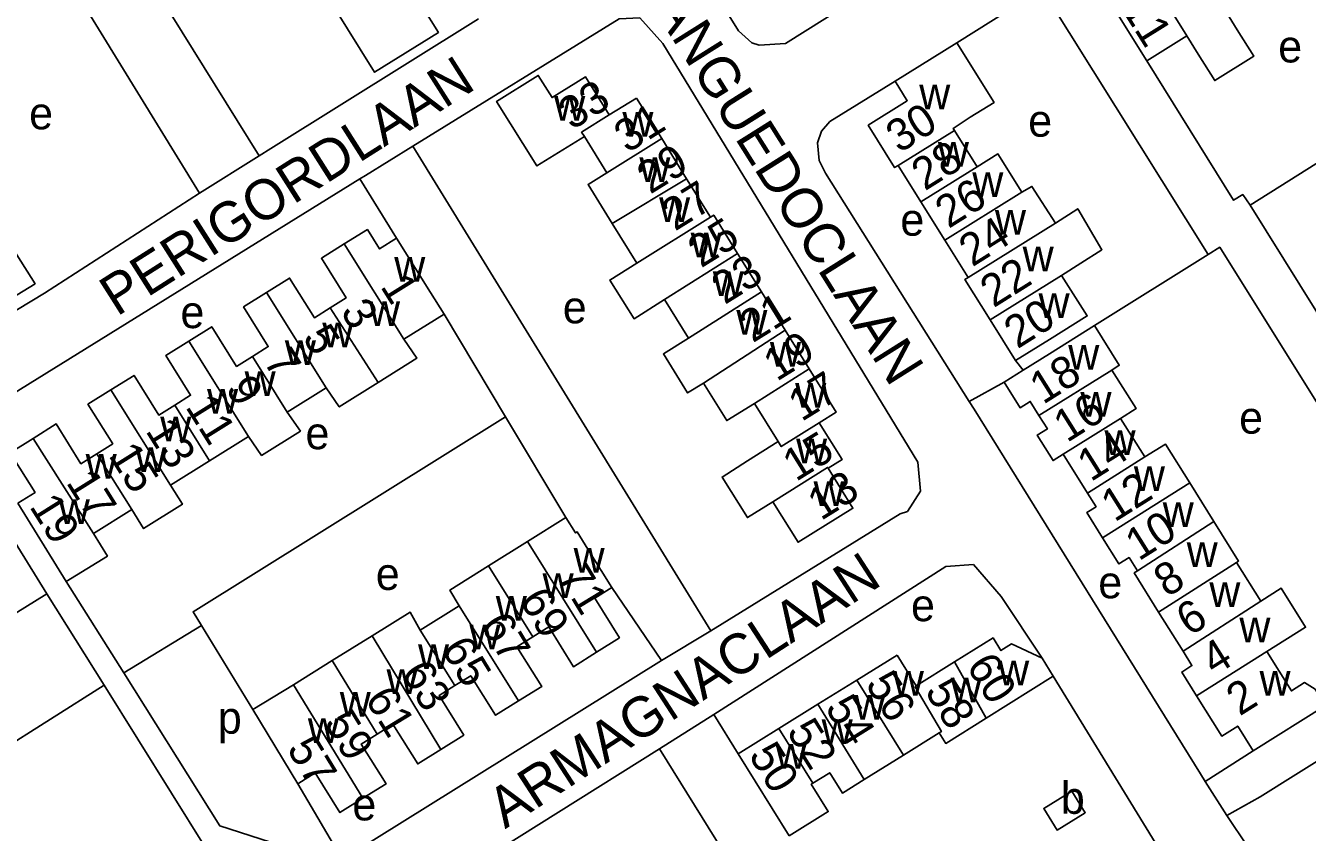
# Model space of a CAD drawing. Extents: x 157768 to 159790, y 387230 to 389604.
# Drawn here: x 158424 to 158583.5, y 388082.5 to 388182.9 of the extents above; entities that cross this region are included whole.
import ezdxf

# ---------------------------------------------------------------- set-up
doc = ezdxf.new("R2010")
doc.units = 0
for name, color, linetype in [('BLT_Basislijn', 7, 'Continuous'), ('BLT_Bebouwing', 7, 'Continuous'), ('BLT_Centroide', 7, 'Continuous'), ('BLT_Huisnummer', 7, 'Continuous'), ('BLT_Huisnummer_ tussenligend', 7, 'Continuous'), ('BLT_Onderverdeling_panden', 7, 'Continuous'), ('BLT_Straatnaam', 7, 'Continuous')]:
    doc.layers.add(name, color=color, linetype=linetype)

msp = doc.modelspace()

# ---------------------------------------------------------------- linework, layer by layer
at = {"layer": 'BLT_Basislijn'}
for p, q in [((158436.28, 388193.58), (158453.03, 388166.65)), ((158428.99, 388189.09), (158445.59, 388162)), ((158550.48, 388187.4), (158539.86, 388180.73)), ((158550.48, 388187.4), (158571.14, 388154.4)), ((158576.33, 388160.51), (158592.73, 388170.86)), ((158472.14, 388167.87), (158509.22, 388107.54)), ((158445.59, 388162), (158453.03, 388166.65)), ((158465.57, 388163.8), (158416.78, 388133.56)), ((158470.14, 388156.41), (158465.57, 388163.8)), ((158571.14, 388154.4), (158556.99, 388145.54)), ((158476.05, 388146.97), (158483.7, 388134.19)), ((158548.1, 388139.99), (158547.15, 388141.17)), ((158545.72, 388138.51), (158541.4, 388136.1)), ((158483.7, 388134.19), (158491.2, 388121.66)), ((158429.02, 388113.68), (158436.19, 388102.31)), ((158503.11, 388103.84), (158496.93, 388112.95)), ((158426.61, 388112.17), (158433.74, 388100.78)), ((158445.86, 388108.21), (158436.19, 388102.31)), ((158452.25, 388097.74), (158445.86, 388108.21)), ((158509.22, 388107.54), (158503.11, 388103.84)), ((158433.74, 388100.78), (158395.24, 388076.43)), ((158502.83, 388092.88), (158509.63, 388097.12)), ((158512.63, 388092.24), (158509.63, 388097.12)), ((158544.39, 388026.21), (158502.83, 388092.88)), ((158570.76, 388088.79), (158576.73, 388092.61)), ((158463.63, 388078.71), (158457.86, 388088.53)), ((158570.76, 388088.79), (158573.46, 388084.58))]:
    msp.add_line(p, q, dxfattribs=at)
for points in [[(158547.57, 388198.9), (158518.51, 388180.63), (158515.25, 388180.43), (158514.36, 388180.7), (158512.7, 388182.23), (158508.37, 388189.2), (158509.52, 388189.92)], [(158453.03, 388166.65), (158454.49, 388167.56), (158480.34, 388183.69)], [(158472.14, 388167.87), (158497.85, 388183.7), (158500.4, 388183.83), (158503.27, 388180.63), (158534.99, 388128.52), (158535.32, 388124.94), (158533.71, 388122.42), (158532.81, 388122.1), (158509.22, 388107.54)], [(158576.33, 388160.51), (158575.42, 388161.84), (158574.28, 388161.13), (158563.49, 388178.46)], [(158532.17, 388175.93), (158524.05, 388170.92), (158522.99, 388169.74), (158522.53, 388168.26), (158522.72, 388166.06), (158523.5, 388164.5), (158541.4, 388136.1)], [(158395.91, 388168.42), (158411.29, 388143.91), (158412.49, 388143.4), (158416.19, 388143.49), (158426.31, 388149.56), (158445.59, 388162)], [(158472.14, 388167.87), (158466.26, 388164.23), (158465.57, 388163.8)], [(158576.33, 388160.51), (158605.06, 388114.46), (158610.96, 388118.11), (158616.41, 388116.75), (158618.88, 388112.75)], [(158585.71, 388098.25), (158601.85, 388108.41), (158572.56, 388155.28), (158571.14, 388154.4)], [(158541.4, 388136.1), (158542.01, 388135.15), (158570.15, 388089.76), (158570.76, 388088.79)], [(158445.86, 388108.21), (158444.8, 388109.93), (158483.7, 388134.19)], [(158509.63, 388097.12), (158538.5, 388115.54), (158541.92, 388115.8), (158545.37, 388111.83), (158550.45, 388104.15)], [(158618.88, 388112.75), (158577.61, 388086.89), (158573.46, 388084.58)], [(158503.11, 388103.84), (158464.46, 388079.77), (158464.09, 388079.58), (158463.63, 388078.71)], [(158436.19, 388102.31), (158448.14, 388083.28), (158463.43, 388078.34)], [(158551.85, 388101.9), (158581.6, 388053.35), (158581.69, 388051.02), (158580.67, 388049.28), (158574.94, 388045.64)], [(158433.74, 388100.78), (158446.31, 388080.65), (158463.81, 388074.86)], [(158502.83, 388092.88), (158477.73, 388077.1), (158475.97, 388074.87), (158475.84, 388072.59), (158476.35, 388071.14), (158490.02, 388048.65), (158497.8, 388036.83), (158512.86, 388012.82), (158514.89, 388011.22), (158518.52, 388010.62), (158520.52, 388010.8), (158521.92, 388011.98)], [(158581.28, 388072.88), (158573.46, 388084.58)]]:
    msp.add_lwpolyline(points, dxfattribs=at)
at = {"layer": 'BLT_Bebouwing'}
for p, q in [((158558.84, 388185.9), (158563.49, 388178.46)), ((158539.86, 388180.73), (158532.17, 388175.93)), ((158496.57, 388171.77), (158500, 388173.84)), ((158503.12, 388168.81), (158500, 388173.84)), ((158496.29, 388164.55), (158493.5, 388169.05)), ((158506.22, 388163.8), (158503.12, 388168.81)), ((158539.55, 388169.83), (158542.38, 388165.28)), ((158532.54, 388165.46), (158535.36, 388160.95)), ((158509.19, 388159.02), (158506.22, 388163.8)), ((158535.36, 388160.95), (158538.34, 388156.17)), ((158500.02, 388153.31), (158496.97, 388158.24)), ((158538.34, 388156.17), (158541.24, 388151.53)), ((158515.54, 388149.73), (158512.57, 388154.51)), ((158518.5, 388144.95), (158515.54, 388149.73)), ((158506.46, 388143.96), (158503.48, 388148.76)), ((158471.05, 388143.84), (158476.05, 388146.97)), ((158521.46, 388140.17), (158518.5, 388144.95)), ((158544, 388146.23), (158547.15, 388141.17)), ((158545.72, 388138.51), (158548.1, 388139.99)), ((158456.53, 388134.76), (158461.37, 388137.79)), ((158517.62, 388131.1), (158514.67, 388135.85)), ((158563.24, 388129.19), (158560.23, 388133.99)), ((158446.85, 388128.71), (158451.69, 388131.74)), ((158513.81, 388128.7), (158517.62, 388131.1)), ((158556.1, 388124.69), (158553.09, 388129.53)), ((158442.01, 388125.69), (158446.85, 388128.71)), ((158429.02, 388113.68), (158423, 388123.43)), ((158432.4, 388119.68), (158437.17, 388122.66)), ((158426.61, 388112.17), (158420.56, 388121.91)), ((158481.59, 388115.65), (158486.44, 388118.68)), ((158577.67, 388111.25), (158574.66, 388116.07)), ((158564.96, 388109.87), (158561.92, 388114.75)), ((158473.07, 388107.65), (158477.92, 388110.68)), ((158568, 388105), (158564.96, 388109.87)), ((158462.13, 388103.84), (158467.08, 388106.93)), ((158457.31, 388100.82), (158462.13, 388103.84)), ((158532.41, 388104.54), (158527.39, 388101.42)), ((158532.41, 388104.54), (158534.79, 388100.71)), ((158539.57, 388103.69), (158534.79, 388100.71)), ((158551.85, 388101.9), (158550.45, 388104.15)), ((158543.51, 388096.69), (158551.85, 388101.9)), ((158527.39, 388101.42), (158522.54, 388098.41)), ((158457.86, 388088.53), (158452.25, 388097.74)), ((158522.54, 388098.41), (158517.7, 388095.4)), ((158585.71, 388098.25), (158576.73, 388092.61)), ((158517.7, 388095.4), (158512.63, 388092.24)), ((158533.21, 388092.08), (158537.66, 388094.84)), ((158528.33, 388089.04), (158533.21, 388092.08))]:
    msp.add_line(p, q, dxfattribs=at)
for points in [[(158471.76, 388190.91), (158474.73, 388186.14), (158473.31, 388185.25), (158475.33, 388182.01), (158467.39, 388177.06), (158462.24, 388185.33), (158464.81, 388186.92)], [(158568.49, 388181.58), (158569.89, 388179.33), (158571.95, 388176.02), (158576.79, 388179.04), (158574.73, 388182.35), (158573.07, 388185.02)], [(158563.49, 388178.46), (158568.49, 388181.58)], [(158541.5, 388171.46), (158544.49, 388173.3), (158539.86, 388180.73)], [(158496.57, 388171.77), (158493.64, 388176.49), (158489.49, 388173.9), (158487.77, 388176.66), (158482.58, 388173.42), (158487.6, 388165.4), (158493.5, 388169.05)], [(158532.17, 388175.93), (158533.68, 388173.51), (158528.82, 388170.47), (158532.11, 388165.19), (158532.54, 388165.46)], [(158539.55, 388169.83), (158539.4, 388170.06), (158541.5, 388171.46)], [(158542.38, 388165.28), (158544.96, 388166.89), (158547.92, 388162.15)], [(158496.97, 388158.24), (158493.96, 388163.1), (158496.29, 388164.55)], [(158547.92, 388162.15), (158549.2, 388162.86), (158552.11, 388158.29)], [(158512.57, 388154.51), (158509.61, 388159.29), (158509.19, 388159.02)], [(158552.11, 388158.29), (158554.9, 388160.07), (158557.9, 388154.97), (158555.28, 388153.3), (158552.87, 388151.76)], [(158463.63, 388155.7), (158466.5, 388157.49), (158468.01, 388155.08), (158470.14, 388156.41)], [(158421.11, 388157.17), (158425.15, 388150.75), (158420.9, 388148.11), (158419.87, 388149.74), (158414.83, 388146.57), (158411.84, 388151.33)], [(158470.14, 388156.41), (158474.37, 388149.65), (158476.05, 388146.97)], [(158461.88, 388147.74), (158463.85, 388148.98), (158460.77, 388153.91), (158463.63, 388155.7)], [(158503.48, 388148.76), (158499.69, 388146.38), (158496.66, 388151.2), (158500.02, 388153.31)], [(158453.95, 388149.65), (158456.82, 388151.44), (158459.9, 388146.51), (158461.88, 388147.74)], [(158541.24, 388151.53), (158540.85, 388151.29), (158544, 388146.23)], [(158547.15, 388141.17), (158551.4, 388143.82), (158556.07, 388146.74), (158552.87, 388151.76)], [(158452.2, 388141.69), (158454.17, 388142.93), (158451.09, 388147.86), (158453.95, 388149.65)], [(158444.27, 388143.6), (158447.14, 388145.39), (158450.22, 388140.45), (158452.2, 388141.69)], [(158548.1, 388139.99), (158551.37, 388142.03), (158556.99, 388145.54)], [(158559.15, 388140), (158560.07, 388140.6), (158556.99, 388145.54)], [(158442.52, 388135.64), (158444.49, 388136.87), (158441.41, 388141.81), (158444.27, 388143.6)], [(158467.83, 388138.45), (158472.65, 388141.46), (158471.05, 388143.84)], [(158508.32, 388138.38), (158506.35, 388137.16), (158503.33, 388142), (158506.46, 388143.96)], [(158522.71, 388133.44), (158524.82, 388134.75), (158521.46, 388140.17)], [(158560.23, 388133.99), (158562.16, 388135.2), (158559.15, 388140)], [(158434.59, 388137.55), (158437.46, 388139.34), (158440.54, 388134.4), (158442.52, 388135.64)], [(158461.37, 388137.79), (158462.99, 388135.42), (158467.83, 388138.45)], [(158514.67, 388135.85), (158511.21, 388133.71), (158508.32, 388138.38)], [(158550.07, 388134.36), (158548.99, 388136.1), (158547.71, 388135.31), (158545.72, 388138.51)], [(158432.84, 388129.59), (158434.82, 388130.82), (158431.73, 388135.75), (158434.59, 388137.55)], [(158451.69, 388131.74), (158453.33, 388129.38), (158458.16, 388132.4), (158456.53, 388134.76)], [(158553.09, 388129.53), (158551.83, 388128.73), (158549.85, 388131.9), (158551.12, 388132.68), (158550.07, 388134.36)], [(158424.92, 388131.49), (158427.78, 388133.29), (158430.86, 388128.35), (158432.84, 388129.59)], [(158523.83, 388127.79), (158525.56, 388128.86), (158522.71, 388133.44)], [(158423, 388123.43), (158425.14, 388124.77), (158422.05, 388129.7), (158424.92, 388131.49)], [(158568.83, 388125.96), (158565.83, 388130.76), (158563.24, 388129.19)], [(158516.96, 388123.62), (158513.8, 388121.65), (158510.64, 388126.69), (158513.81, 388128.7)], [(158523.83, 388127.79), (158526.92, 388122.81), (158520.09, 388118.57), (158516.96, 388123.62)], [(158437.17, 388122.66), (158438.65, 388120.28), (158443.49, 388123.31), (158442.01, 388125.69)], [(158571.82, 388121.15), (158568.83, 388125.96)], [(158557.99, 388119.11), (158556.02, 388122.27), (158557.17, 388122.99), (158556.1, 388124.69)], [(158486.44, 388118.68), (158491.2, 388121.66)], [(158491.2, 388121.66), (158492.4, 388119.73), (158492.61, 388119.86), (158494.28, 388117.19), (158496.93, 388112.95)], [(158574.66, 388116.07), (158574.9, 388116.22), (158571.82, 388121.15)], [(158432.4, 388119.68), (158434.15, 388116.85), (158429.02, 388113.68)], [(158562.33, 388115), (158561.29, 388116.67), (158560.01, 388115.87), (158557.99, 388119.11)], [(158477.92, 388110.68), (158476.77, 388112.63), (158481.59, 388115.65)], [(158561.92, 388114.75), (158561.92, 388114.75), (158562.33, 388115)], [(158496.93, 388112.95), (158494.79, 388111.61), (158497.87, 388106.68), (158495.01, 388104.88)], [(158578.41, 388104.97), (158583.24, 388107.99), (158580.21, 388112.84), (158577.67, 388111.25)], [(158421.14, 388109.53), (158421.48, 388108.98), (158426.61, 388112.17)], [(158467.08, 388106.93), (158471.81, 388109.89), (158473.07, 388107.65)], [(158495.01, 388104.88), (158492.14, 388103.09), (158489.06, 388108.03), (158487.08, 388106.79)], [(158487.08, 388106.79), (158485.1, 388105.56), (158488.19, 388100.62), (158485.32, 388098.83)], [(158550.45, 388104.15), (158546.67, 388105.92), (158545.33, 388105.09), (158544.35, 388106.66), (158539.57, 388103.69)], [(158569.69, 388099.46), (158567.84, 388102.42), (158569.11, 388103.22), (158568, 388105)], [(158585.71, 388098.25), (158584.42, 388100.3), (158583.1, 388101.1), (158581.48, 388100.08), (158578.41, 388104.97)], [(158485.32, 388098.83), (158482.45, 388097.04), (158479.37, 388101.97), (158477.39, 388100.74)], [(158452.25, 388097.74), (158457.31, 388100.82)], [(158477.39, 388100.74), (158475.42, 388099.5), (158478.5, 388094.57), (158475.63, 388092.78)], [(158576.73, 388092.61), (158574.8, 388095.7), (158572.81, 388094.46), (158569.69, 388099.46)], [(158475.63, 388092.78), (158472.77, 388090.98), (158469.68, 388095.92), (158467.71, 388094.68)], [(158537.66, 388094.84), (158538.46, 388093.54), (158543.51, 388096.69)], [(158467.71, 388094.68), (158465.73, 388093.45), (158468.82, 388088.51), (158465.95, 388086.72)], [(158512.63, 388092.24), (158516.87, 388085.44), (158518.99, 388082.03)], [(158465.95, 388086.72), (158463.08, 388084.93), (158460, 388089.86), (158457.86, 388088.53)], [(158521.93, 388088.59), (158524.03, 388089.89), (158525.61, 388087.35), (158528.33, 388089.04)], [(158518.99, 388082.03), (158523.85, 388085.05), (158521.73, 388088.46), (158521.93, 388088.59)]]:
    msp.add_lwpolyline(points, dxfattribs=at)
msp.add_lwpolyline([(158554.17, 388087.61), (158555.82, 388084.92), (158552.33, 388082.76), (158550.67, 388085.46)], close=True, dxfattribs=at)
at = {"layer": 'BLT_Onderverdeling_panden'}
for p, q in [((158568.49, 388181.58), (158563.85, 388189.02)), ((158496.29, 388164.55), (158503.12, 388168.81)), ((158532.54, 388165.46), (158539.55, 388169.83)), ((158496.97, 388158.24), (158506.22, 388163.8)), ((158535.36, 388160.95), (158542.38, 388165.28)), ((158538.34, 388156.17), (158547.92, 388162.15)), ((158500.02, 388153.31), (158509.19, 388159.02)), ((158541.24, 388151.53), (158552.11, 388158.29)), ((158463.63, 388155.7), (158471.05, 388143.84)), ((158503.48, 388148.76), (158512.57, 388154.51)), ((158544, 388146.23), (158552.87, 388151.76)), ((158453.95, 388149.65), (158461.37, 388137.79)), ((158506.46, 388143.96), (158515.54, 388149.73)), ((158461.88, 388147.74), (158467.83, 388138.45)), ((158508.32, 388138.38), (158518.5, 388144.95)), ((158444.27, 388143.6), (158451.69, 388131.74)), ((158452.2, 388141.69), (158456.53, 388134.76)), ((158514.67, 388135.85), (158521.46, 388140.17)), ((158550.07, 388134.36), (158559.15, 388140)), ((158434.59, 388137.55), (158442.01, 388125.69)), ((158442.52, 388135.64), (158446.85, 388128.71)), ((158553.09, 388129.53), (158560.23, 388133.99)), ((158424.92, 388131.49), (158432.4, 388119.68)), ((158432.84, 388129.59), (158437.17, 388122.66)), ((158556.1, 388124.69), (158563.24, 388129.19)), ((158557.99, 388119.11), (158568.83, 388125.96)), ((158562.33, 388115), (158571.82, 388121.15)), ((158495.01, 388104.88), (158486.44, 388118.68)), ((158564.96, 388109.87), (158574.66, 388116.07)), ((158487.08, 388106.79), (158481.59, 388115.65)), ((158568, 388105), (158577.67, 388111.25)), ((158485.32, 388098.83), (158477.92, 388110.68)), ((158475.63, 388092.78), (158467.08, 388106.93)), ((158477.39, 388100.74), (158473.07, 388107.65)), ((158569.69, 388099.46), (158578.41, 388104.97)), ((158467.71, 388094.68), (158462.13, 388103.84)), ((158539.57, 388103.69), (158543.51, 388096.69)), ((158465.95, 388086.72), (158457.31, 388100.82)), ((158533.21, 388092.08), (158527.39, 388101.42)), ((158528.33, 388089.04), (158522.54, 388098.41)), ((158521.93, 388088.59), (158517.7, 388095.4))]:
    msp.add_line(p, q, dxfattribs=at)
for points in [[(158493.5, 388169.05), (158493.16, 388169.6), (158496.57, 388171.77)], [(158517.62, 388131.1), (158518, 388130.47), (158522.71, 388133.44)], [(158523.83, 388127.79), (158523.77, 388127.88), (158516.96, 388123.62)], [(158534.79, 388100.71), (158534.65, 388100.6), (158537.93, 388095.02), (158537.66, 388094.84)]]:
    msp.add_lwpolyline(points, dxfattribs=at)

# ---------------------------------------------------------------- texts
at = {"layer": 'BLT_Centroide'}
for s, p in [('e', (158579.84, 388178.28)), ('w', (158535.17, 388172.45)), ('w', (158489.74, 388171.03)), ('e', (158424.41, 388169.96)), ('w', (158498.23, 388169.06)), ('e', (158548.73, 388169.04)), ('w', (158537.49, 388165.31)), ('w', (158500.34, 388163.41)), ('w', (158541.77, 388161.53)), ('w', (158502.8, 388158.44)), ('e', (158532.82, 388156.72)), ('w', (158544.59, 388156.84)), ('w', (158506.72, 388154.03)), ('w', (158548.04, 388152.28)), ('w', (158469.84, 388151)), ('w', (158509.48, 388149.22)), ('w', (158550.02, 388146.47)), ('e', (158443.24, 388145.22)), ('w', (158466.7, 388145.48)), ('e', (158490.82, 388145.82)), ('w', (158512.41, 388144.41)), ('w', (158460.89, 388142.84)), ('w', (158456.23, 388140.62)), ('w', (158516.59, 388140.41)), ('w', (158553.71, 388140.03)), ('w', (158451.22, 388136.78)), ('w', (158519.73, 388135.31)), ('w', (158446.55, 388134.58)), ('w', (158555.23, 388134.19)), ('e', (158574.98, 388132.09)), ('w', (158440.72, 388131.12)), ('e', (158458.8, 388130.15)), ('w', (158558.22, 388129.41)), ('w', (158437.61, 388127.33)), ('w', (158519.85, 388128.41)), ('w', (158431.44, 388126.47)), ('w', (158561.88, 388124.94)), ('w', (158522.02, 388123.09)), ('w', (158428.09, 388120.83)), ('w', (158565.47, 388120.47)), ('w', (158492.16, 388114.8)), ('w', (158568.45, 388115.5)), ('e', (158467.55, 388112.64)), ('w', (158488.3, 388111.62)), ('e', (158557.45, 388111.6)), ('w', (158571.27, 388110.53)), ('w', (158482.48, 388108.8)), ('e', (158534.15, 388108.75)), ('w', (158479.2, 388105.25)), ('w', (158575.01, 388106.12)), ('w', (158472.8, 388102.81)), ('w', (158544.99, 388100.76)), ('w', (158468.88, 388099.69)), ('w', (158531.89, 388099.5)), ('w', (158539.08, 388098.66)), ('w', (158577.51, 388099.5)), ('w', (158463.06, 388096.88)), ('w', (158527.08, 388096.5)), ('p', (158447.89, 388094.75)), ('w', (158459.09, 388093.61)), ('w', (158523.03, 388093.45)), ('w', (158517.28, 388090.41)), ('b', (158552.79, 388084.78)), ('e', (158464.63, 388083.96))]:
    msp.add_text(s, height=4, dxfattribs=at).set_placement(p)
at = {"layer": 'BLT_Huisnummer'}
for s, rotation, p in [('11', 301.959, (158560.27, 388184.93)), ('33', 31.8022, (158491.95, 388169.79)), ('30', 32.1698, (158532.69, 388166.92)), ('29', 31.8022, (158501.69, 388161.82)), ('25', 31.8022, (158508.02, 388152.64)), ('24', 32.1698, (158541.77, 388152.77)), ('1', 302.015, (158468.04, 388150.41)), ('21', 31.8022, (158514.45, 388143.32)), ('20', 32.1698, (158547.39, 388142.57)), ('5', 302.015, (158458.35, 388144.04)), ('18', 32.1698, (158550.58, 388135.65)), ('17', 31.8022, (158520.52, 388133.51)), ('9', 302.0344, (158448.77, 388137.71)), ('13', 302.0344, (158438.82, 388132.44)), ('14', 32.1698, (158556.51, 388126.03)), ('13', 31.8022, (158522.93, 388121.19)), ('19', 302.0344, (158424.37, 388123.03)), ('10', 32.1698, (158562.48, 388116.17)), ('71', 301.3446, (158490.15, 388114.32)), ('6', 32.1698, (158568.81, 388106.81)), ('65', 301.3446, (158475.62, 388105.29)), ('60', 301.8766, (158540.96, 388103.17)), ('61', 301.3446, (158466.12, 388099.07)), ('2', 32.1698, (158575.04, 388096.88)), ('54', 301.9637, (158523.37, 388097.97)), ('57', 301.3446, (158456.4, 388092.88)), ('50', 301.9637, (158513.86, 388092.07))]:
    msp.add_text(s, height=4, rotation=rotation, dxfattribs=at).set_placement(p)
at = {"layer": 'BLT_Huisnummer_ tussenligend'}
for s, rotation, p in [('31', 31.8022, (158498.84, 388166.93)), ('28', 32.1698, (158535.87, 388162.23)), ('26', 32.1698, (158538.82, 388157.54)), ('27', 31.8022, (158504.77, 388157.22)), ('23', 31.8022, (158510.96, 388148.08)), ('22', 32.1698, (158544.42, 388147.68)), ('3', 302.015, (158463.07, 388147.28)), ('19', 31.8022, (158517.43, 388138.52)), ('7', 302.0344, (158453.49, 388141.09)), ('11', 302.0344, (158443.78, 388135.43)), ('16', 32.1698, (158553.55, 388130.9)), ('15', 31.8022, (158519.82, 388126.05)), ('15', 302.0344, (158434.21, 388129.4)), ('17', 302.0344, (158428.94, 388126.03)), ('12', 32.1698, (158559.47, 388121.01)), ('8', 32.1698, (158566.01, 388111.65)), ('69', 301.3446, (158485.34, 388111.37)), ('67', 301.3446, (158480.48, 388108.27)), ('4', 32.1698, (158571.92, 388101.89)), ('63', 301.3446, (158470.61, 388102.3)), ('56', 301.9637, (158528.39, 388100.93)), ('58', 301.9637, (158535.79, 388100.03)), ('59', 301.3446, (158461, 388096.11)), ('52', 301.9637, (158518.59, 388095.02))]:
    msp.add_text(s, height=4, rotation=rotation, dxfattribs=at).set_placement(p)
at = {"layer": 'BLT_Straatnaam'}
for s, height, rotation, p in [('LANGUEDOCLAAN', 4.9999, 302.1382, (158499.9, 388188.4)), ('PERIGORDLAAN', 5, 32.4225, (158435.33, 388146.6)), ('ARMAGNACLAAN', 5, 32.9551, (158483.64, 388082.85))]:
    msp.add_text(s, height=height, rotation=rotation, dxfattribs=at).set_placement(p)

doc.saveas('drawing.dxf')
